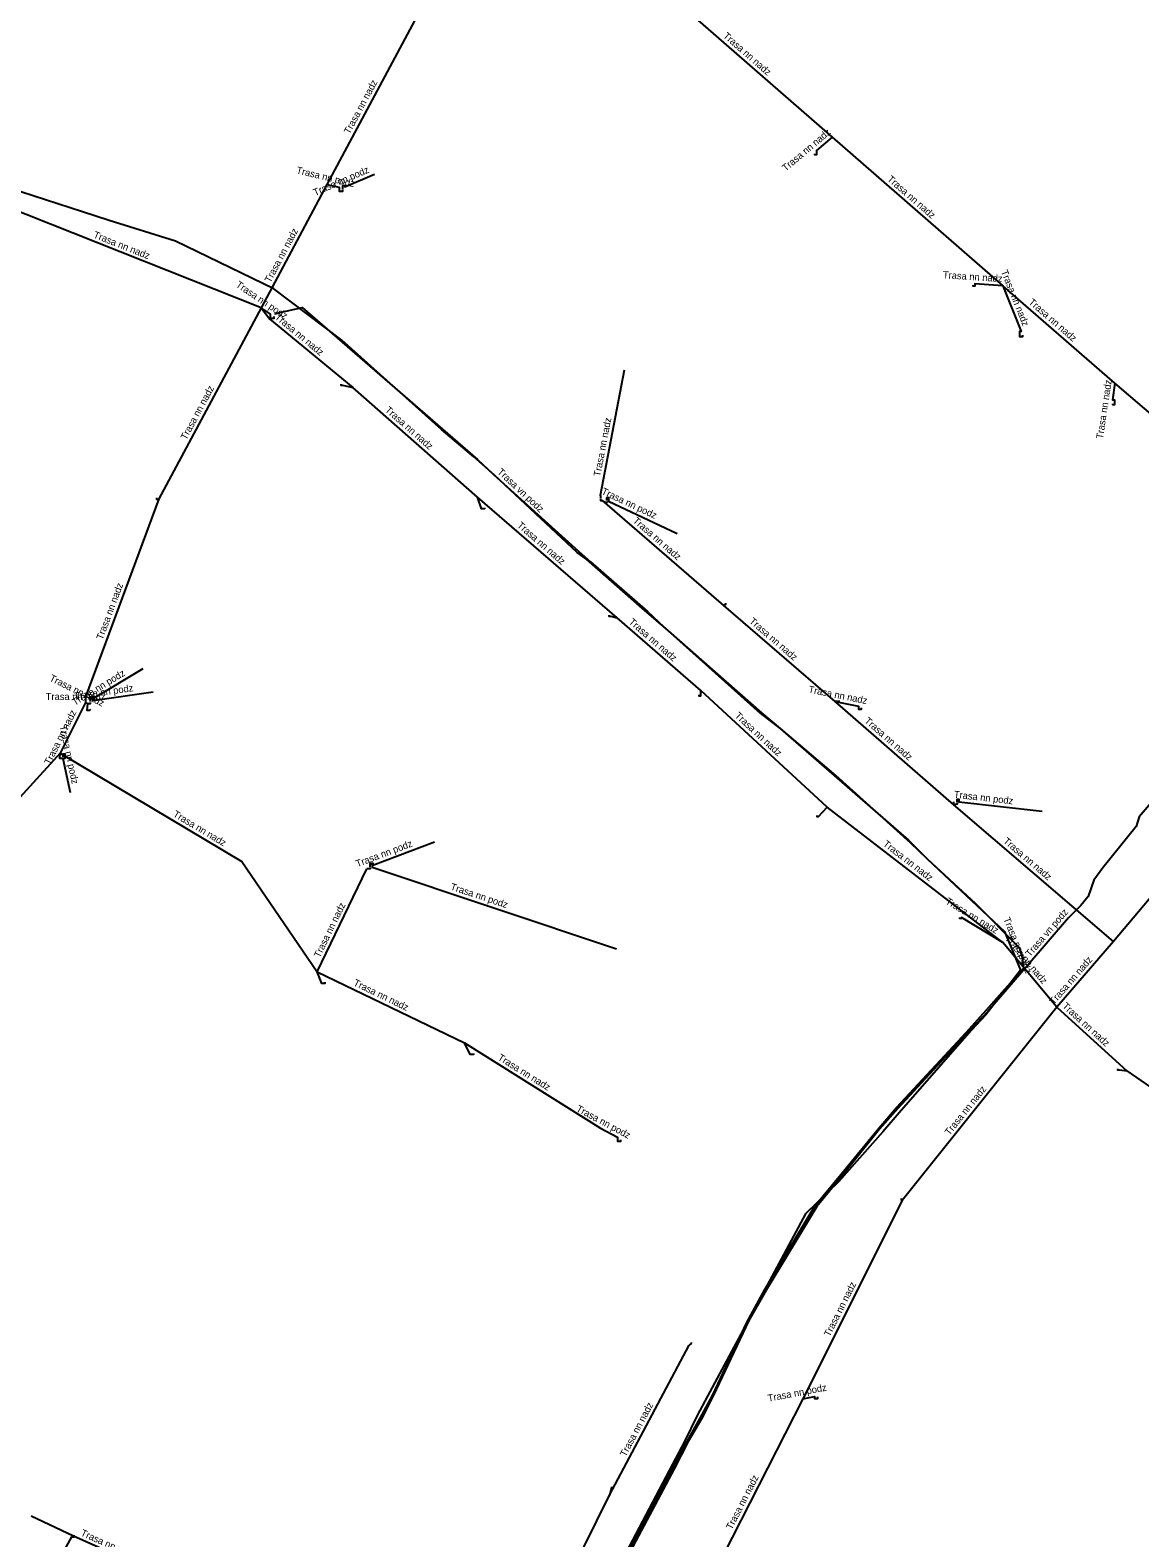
# Model space of a CAD drawing. Extents: x -742082 to -717476, y -1040737 to -1024597.
# Drawn here: x -736004.4 to -735845.4, y -1032569.4 to -1032353.4 of the extents above; entities that cross this region are included whole.
import ezdxf

# ---------------------------------------------------------------- set-up
doc = ezdxf.new("R2010")
doc.units = 0
for name, color, linetype in [('Level 13', 7, 'Continuous'), ('Level 14', 7, 'Continuous'), ('Level 15', 7, 'Continuous'), ('Level 20', 7, 'Continuous'), ('Level 25', 7, 'Continuous')]:
    doc.layers.add(name, color=color, linetype=linetype)

msp = doc.modelspace()

# ---------------------------------------------------------------- linework, layer by layer
at = {"layer": 'Level 13'}
for p, q in [((-735912.11, -1032348.97), (-735889.5, -1032368.71)), ((-735948.59, -1032350.62), (-735961.89, -1032375.47)), ((-735889.5, -1032368.71), (-735865.06, -1032390)), ((-735961.89, -1032375.47), (-735971.32, -1032393.18)), ((-735971.32, -1032393.18), (-736008.26, -1032378.52)), ((-735848.99, -1032403.96), (-735865.06, -1032390)), ((-735971.32, -1032393.18), (-735985.97, -1032420.54)), ((-735940.3, -1032420.3), (-735958.2, -1032404.6)), ((-735829.69, -1032420.46), (-735848.99, -1032403.96)), ((-735920.3, -1032437.6), (-735940.3, -1032420.3)), ((-735905.02, -1032435.82), (-735922.41, -1032420.77)), ((-735889.05, -1032449.57), (-735905.02, -1032435.82)), ((-735908.32, -1032447.98), (-735920.3, -1032437.6)), ((-735890.2, -1032464.7), (-735908.32, -1032447.98)), ((-735996.51, -1032449.69), (-736000.12, -1032456.95)), ((-735996.51, -1032449.69), (-735996.17, -1032449.86)), ((-735872.05, -1032464.4), (-735889.05, -1032449.57)), ((-736000.12, -1032456.95), (-736015.31, -1032473.63)), ((-735865.05, -1032484.09), (-735890.2, -1032464.7)), ((-735963.3, -1032488.3), (-735956.16, -1032473.56)), ((-735857.3, -1032493.37), (-735865.05, -1032484.09)), ((-735849.17, -1032483.94), (-735857.3, -1032493.37)), ((-735963.3, -1032488.3), (-735942.2, -1032498.5)), ((-735857.3, -1032493.37), (-735879.45, -1032521.06)), ((-735857.3, -1032493.37), (-735847.3, -1032502.5)), ((-735942.2, -1032498.5), (-735922.7, -1032510.7)), ((-735847.3, -1032502.5), (-735829.67, -1032514.61)), ((-735879.45, -1032521.06), (-735893.71, -1032549.48)), ((-735921.4, -1032563.3), (-735910, -1032541.8)), ((-735893.71, -1032549.48), (-735907.45, -1032576.44)), ((-735930.1, -1032580.8), (-735921.4, -1032563.3))]:
    msp.add_line(p, q, dxfattribs=at)
for points in [[(-735971.32, -1032393.18), (-735970.08, -1032394.78), (-735958.2, -1032404.6)], [(-735919.3, -1032402.1), (-735922.73, -1032420.05), (-735922.7, -1032420.05), (-735922.7, -1032420.49)], [(-735959.9, -1032404.1), (-735959.9, -1032404.26), (-735959.65, -1032404.26), (-735958.2, -1032404.6)], [(-735985.97, -1032420.54), (-735996.51, -1032448.89), (-735996.51, -1032449.69)], [(-735986.3, -1032420.4), (-735986.3, -1032420.56), (-735986.05, -1032420.56), (-735985.97, -1032420.54)], [(-735939.3, -1032421.8), (-735939.3, -1032421.96), (-735939.75, -1032421.96), (-735940.3, -1032420.3)], [(-735922.7, -1032420.6), (-735922.7, -1032420.76), (-735922.41, -1032420.77)], [(-735921.8, -1032420.9), (-735921.8, -1032421.06), (-735921.96, -1032421.06), (-735922.41, -1032420.77)], [(-735904.8, -1032435.5), (-735904.8, -1032435.66), (-735905.02, -1032435.82)], [(-735921.5, -1032437.2), (-735921.5, -1032437.36), (-735921.24, -1032437.36), (-735920.3, -1032437.6)], [(-735811.36, -1032438.75), (-735832.02, -1032463.59), (-735849.17, -1032483.94)], [(-735908.6, -1032448.6), (-735908.6, -1032448.76), (-735908.34, -1032448.76), (-735908.32, -1032447.98)], [(-735995.8, -1032450.7), (-735995.9, -1032450.86), (-735996.25, -1032450.86), (-735996.17, -1032449.86)], [(-735996.17, -1032449.86), (-735995.8, -1032449.86), (-735995.8, -1032449.7)], [(-735888.54, -1032449.43), (-735888.54, -1032449.59), (-735888.72, -1032449.59), (-735889.05, -1032449.57)], [(-735999.7, -1032457.6), (-735999.7, -1032457.76), (-736000.15, -1032457.76), (-736000.12, -1032456.95)], [(-736000.12, -1032456.95), (-735974.1, -1032472.5), (-735963.3, -1032488.3)], [(-735872.05, -1032464.4), (-735872.09, -1032464.09), (-735872.09, -1032463.96)], [(-735871.6, -1032464.1), (-735871.6, -1032464.26), (-735872.05, -1032464.4)], [(-735891.7, -1032465.9), (-735891.7, -1032466.06), (-735891.45, -1032466.06), (-735890.2, -1032464.7)], [(-735955.7, -1032473.4), (-735955.7, -1032473.56), (-735956.16, -1032473.56)], [(-735962.2, -1032489.8), (-735962.2, -1032489.96), (-735962.65, -1032489.96), (-735963.3, -1032488.3)], [(-735940.9, -1032500), (-735940.9, -1032500.16), (-735941.35, -1032500.16), (-735942.2, -1032498.5)], [(-735848.6, -1032502.2), (-735848.6, -1032502.36), (-735848.34, -1032502.36), (-735847.3, -1032502.5)], [(-735879.6, -1032520.8), (-735879.6, -1032520.96), (-735879.45, -1032521.06)], [(-735909.7, -1032541.4), (-735909.7, -1032541.56), (-735910, -1032541.8)], [(-735921.1, -1032562.1), (-735921.1, -1032562.26), (-735921.4, -1032563.3)], [(-735979.1, -1032577.7), (-735998.23, -1032569.17), (-736004.3, -1032566.3)]]:
    msp.add_lwpolyline(points, dxfattribs=at)
at = {"layer": 'Level 14'}
msp.add_line((-735849.17, -1032483.94), (-735872.05, -1032464.4), dxfattribs=at)
for points in [[(-735889.5, -1032368.71), (-735891.74, -1032370.6), (-735891.74, -1032371.26), (-735892, -1032371.26), (-735892, -1032371.1)], [(-735865.06, -1032390), (-735869.04, -1032389.72), (-735869.04, -1032390.06), (-735869.3, -1032390.06), (-735869.3, -1032389.9)], [(-735865.06, -1032390), (-735862.44, -1032396.55), (-735862.65, -1032396.55), (-735862.65, -1032397.26), (-735862.2, -1032397.26), (-735862.2, -1032397.1)], [(-735848.99, -1032403.96), (-735849.35, -1032406.35), (-735849.05, -1032406.35), (-735849.05, -1032407.06), (-735849.3, -1032407.06), (-735849.3, -1032406.9)], [(-735889.05, -1032449.57), (-735885.75, -1032450.23), (-735885.75, -1032450.66), (-735885.3, -1032450.66), (-735885.3, -1032450.5)], [(-735865.05, -1032484.09), (-735870.95, -1032480.52), (-735870.95, -1032480.66), (-735871.2, -1032480.66), (-735871.2, -1032480.5)]]:
    msp.add_lwpolyline(points, dxfattribs=at)
at = {"layer": 'Level 15'}
for points in [[(-735961.89, -1032375.47), (-735960.15, -1032375.89), (-735960.15, -1032376.46), (-735959.6, -1032376.46), (-735959.6, -1032376.2)], [(-735959.6, -1032376.09), (-735959.6, -1032375.65), (-735959.34, -1032375.65), (-735959.34, -1032375.85), (-735955.1, -1032374)], [(-735969.51, -1032394.4), (-735969.51, -1032394.67), (-735969.99, -1032394.67), (-735969.99, -1032394.08), (-735971.32, -1032393.18)], [(-735969.28, -1032394.11), (-735969.28, -1032393.96), (-735965.47, -1032393.1), (-735940.31, -1032414.88), (-735938.01, -1032417.03), (-735925.87, -1032428.05), (-735924.14, -1032429.58), (-735915.95, -1032436.69), (-735913.63, -1032438.88), (-735899.81, -1032451.26), (-735896.91, -1032453.47), (-735878.56, -1032469.43), (-735875.82, -1032472.15), (-735864.79, -1032482.55), (-735862.53, -1032488.07), (-735867.5, -1032494.47), (-735869.55, -1032496.64), (-735879.62, -1032508.19), (-735882.26, -1032511.25), (-735888.53, -1032518.37), (-735893.32, -1032522.99), (-735907.37, -1032549.11), (-735908.83, -1032551.89), (-735910.65, -1032555.61), (-735912.38, -1032558.84), (-735926.24, -1032585.16)], [(-735921.8, -1032420.79), (-735921.8, -1032420.35), (-735921.54, -1032420.35), (-735921.54, -1032420.87), (-735911.7, -1032425.5)], [(-735988.3, -1032444.9), (-735995.34, -1032449.16), (-735995.34, -1032448.95), (-735995.81, -1032448.95), (-735995.81, -1032449.59)], [(-735995.79, -1032449.59), (-735995.79, -1032449.05), (-735995.44, -1032449.05), (-735995.44, -1032449.43), (-735986.8, -1032448.2)], [(-735999.7, -1032457.49), (-735999.7, -1032457.05), (-735999.44, -1032457.05), (-735999.44, -1032457.76), (-735999.72, -1032457.76), (-735998.7, -1032462.6)], [(-735871.6, -1032463.99), (-735871.6, -1032463.55), (-735871.34, -1032463.55), (-735871.34, -1032463.94), (-735859.4, -1032465.3)], [(-735955.71, -1032473.29), (-735955.71, -1032472.75), (-735955.34, -1032472.75), (-735955.34, -1032473.03), (-735946.5, -1032469.7)], [(-735955.69, -1032473.29), (-735955.69, -1032472.85), (-735955.44, -1032472.85), (-735955.44, -1032473.32), (-735920.4, -1032485)], [(-735922.7, -1032510.7), (-735920.25, -1032512.01), (-735920.25, -1032512.56), (-735919.8, -1032512.56), (-735919.8, -1032512.4)], [(-735893.71, -1032549.48), (-735892.05, -1032549.17), (-735892.05, -1032549.46), (-735891.54, -1032549.46), (-735891.54, -1032549.19)], [(-735989.59, -1032577.47), (-735989.59, -1032576.93), (-735990.11, -1032576.93), (-735990.11, -1032577.67), (-735999.99, -1032572.04), (-735998.44, -1032569.25), (-735998.11, -1032569.25), (-735998.11, -1032569.04)]]:
    msp.add_lwpolyline(points, dxfattribs=at)
at = {"layer": 'Level 25'}
for points in [[(-735918.58, -1032571.32), (-735912.19, -1032559.12), (-735910.3, -1032555.58), (-735908.41, -1032552.25), (-735906.65, -1032549), (-735901.73, -1032538.54), (-735899.15, -1032533.84), (-735891.92, -1032521.81), (-735888.26, -1032517.34), (-735882.82, -1032510.71), (-735880.27, -1032507.73), (-735870.26, -1032496.93), (-735867.43, -1032493.79), (-735862.03, -1032487.74), (-735862.21, -1032486.21), (-735862.62, -1032484.9), (-735868.92, -1032478.57), (-735875.86, -1032472.16), (-735878.24, -1032469.89), (-735888.97, -1032460.17), (-735896.91, -1032453.42), (-735899.59, -1032451.18), (-735912.96, -1032439.45), (-735916.71, -1032436.2), (-735924.67, -1032429.24), (-735926.04, -1032428.22), (-735937.9, -1032417.15), (-735940.86, -1032414.51), (-735945.5, -1032410.58), (-735959.76, -1032397.8), (-735969.53, -1032390.42), (-735983.62, -1032383.63), (-735993.09, -1032380.63), (-735996.92, -1032379.42), (-736019.96, -1032371.98)], [(-735842.95, -1032463.08), (-735845.53, -1032466.1), (-735845.96, -1032467.46), (-735850.72, -1032473.41), (-735852.01, -1032475.18), (-735852.84, -1032477.5), (-735853.86, -1032478.81), (-735855.63, -1032480.58), (-735861.45, -1032487.36), (-735867.21, -1032493.98), (-735870.46, -1032497.42), (-735880.08, -1032507.88), (-735882.72, -1032510.85), (-735888.07, -1032517.54), (-735891.7, -1032521.92), (-735898.96, -1032533.92), (-735901.42, -1032538.27), (-735906.55, -1032549.04), (-735908.23, -1032552.35), (-735910.13, -1032555.58), (-735912.15, -1032559.53), (-735918.46, -1032571.38)]]:
    msp.add_lwpolyline(points, dxfattribs=at)

# ---------------------------------------------------------------- texts
at = {"layer": 'Level 20'}
for s, rotation, p in [('Trasa nn nadz', 318.8769, (-735905.21, -1032354.33)), ('Trasa nn nadz', 61.8438, (-735958.65, -1032368.35)), ('Trasa nn nadz', 40.108, (-735896.16, -1032373.67)), ('Trasa nn podz', 346.3946, (-735966.34, -1032373.88)), ('Trasa nn podz', 23.4988, (-735963.6, -1032377.15)), ('Trasa nn nadz', 318.9405, (-735881.69, -1032374.85)), ('Trasa nn nadz', 61.9661, (-735970, -1032389.64)), ('Trasa nn nadz', 338.3539, (-735995.45, -1032383.07)), ('Trasa nn nadz', 356.046, (-735873.66, -1032388.9)), ('Trasa nn nadz', 291.8014, (-735865.34, -1032387.96)), ('Trasa nn podz', 326.0751, (-735975.04, -1032390.08)), ('Trasa nn nadz', 319.0192, (-735861.44, -1032392.48)), ('Trasa nn nadz', 320.421, (-735969.45, -1032394.65)), ('Trasa nn nadz', 81.4898, (-735850.7, -1032412)), ('Trasa nn nadz', 61.833, (-735982.05, -1032412.17)), ('Trasa nn nadz', 318.7462, (-735953.65, -1032407.93)), ('Trasa nn nadz', 79.1901, (-735922.73, -1032417.39)), ('Trasa vn podz', 316.9431, (-735937.56, -1032416.78)), ('Trasa nn podz', 334.7988, (-735922.65, -1032419.79)), ('Trasa nn nadz', 319.1258, (-735918.14, -1032423.8)), ('Trasa nn nadz', 319.1402, (-735934.73, -1032424.46)), ('Trasa nn nadz', 69.6004, (-735994.04, -1032440.81)), ('Trasa nn nadz', 319.0929, (-735918.73, -1032438.3)), ('Trasa nn nadz', 319.2719, (-735901.47, -1032438.21)), ('Trasa nn nadz', 333.6408, (-736001.75, -1032446.54)), ('Trasa nn podz', 31.1851, (-735998.02, -1032450.2)), ('Trasa nn podz', 8.1302, (-735998.05, -1032449.3)), ('Trasa nn nadz', 348.6901, (-735892.96, -1032448.28)), ('Trasa nn nadz', 63.5705, (-736001.56, -1032458.73)), ('Trasa nn nadz', 317.3011, (-735903.54, -1032451.71)), ('Trasa nn podz', 281.9441, (-736000.2, -1032453.1)), ('Trasa nn nadz', 318.9001, (-735884.96, -1032452.48)), ('Trasa nn podz', 353.5066, (-735872.1, -1032463.35)), ('Trasa nn nadz', 329.1367, (-735984.04, -1032465.98)), ('Trasa nn podz', 20.6235, (-735957.54, -1032473.32)), ('Trasa nn nadz', 322.3687, (-735882.3, -1032470.16)), ('Trasa nn nadz', 319.502, (-735865.07, -1032469.71)), ('Trasa nn podz', 341.5651, (-735944.28, -1032476.51)), ('Trasa nn nadz', 64.1546, (-735962.92, -1032486.37)), ('Trasa nn nadz', 328.7672, (-735873.35, -1032478.47)), ('Trasa nn podz', 292.2781, (-735865, -1032480.73)), ('Trasa vn podz', 49.3653, (-735861.14, -1032486.24)), ('Trasa nn nadz', 309.8662, (-735864.82, -1032483.58)), ('Trasa nn nadz', 49.234, (-735857.72, -1032493.09)), ('Trasa nn nadz', 334.2003, (-735958.19, -1032490.21)), ('Trasa nn nadz', 317.6039, (-735856.61, -1032493.33)), ('Trasa nn nadz', 327.9682, (-735937.51, -1032500.84)), ('Trasa nn nadz', 51.3427, (-735872.69, -1032511.81)), ('Trasa nn podz', 331.8214, (-735926.27, -1032508.22)), ('Trasa nn nadz', 63.3544, (-735889.85, -1032540.67)), ('Trasa nn podz', 10.7051, (-735898.63, -1032549.9)), ('Trasa nn nadz', 62.066, (-735919.09, -1032557.87)), ('Trasa nn nadz', 62.9946, (-735903.88, -1032568.33)), ('Trasa nn nadz', 335.9578, (-735997.27, -1032569.05))]:
    msp.add_text(s, height=1, rotation=rotation, dxfattribs=at).set_placement(p)
msp.add_text('Trasa nn nadz', height=1, dxfattribs=at).set_placement((-736002.19, -1032449.36))

doc.saveas('drawing.dxf')
